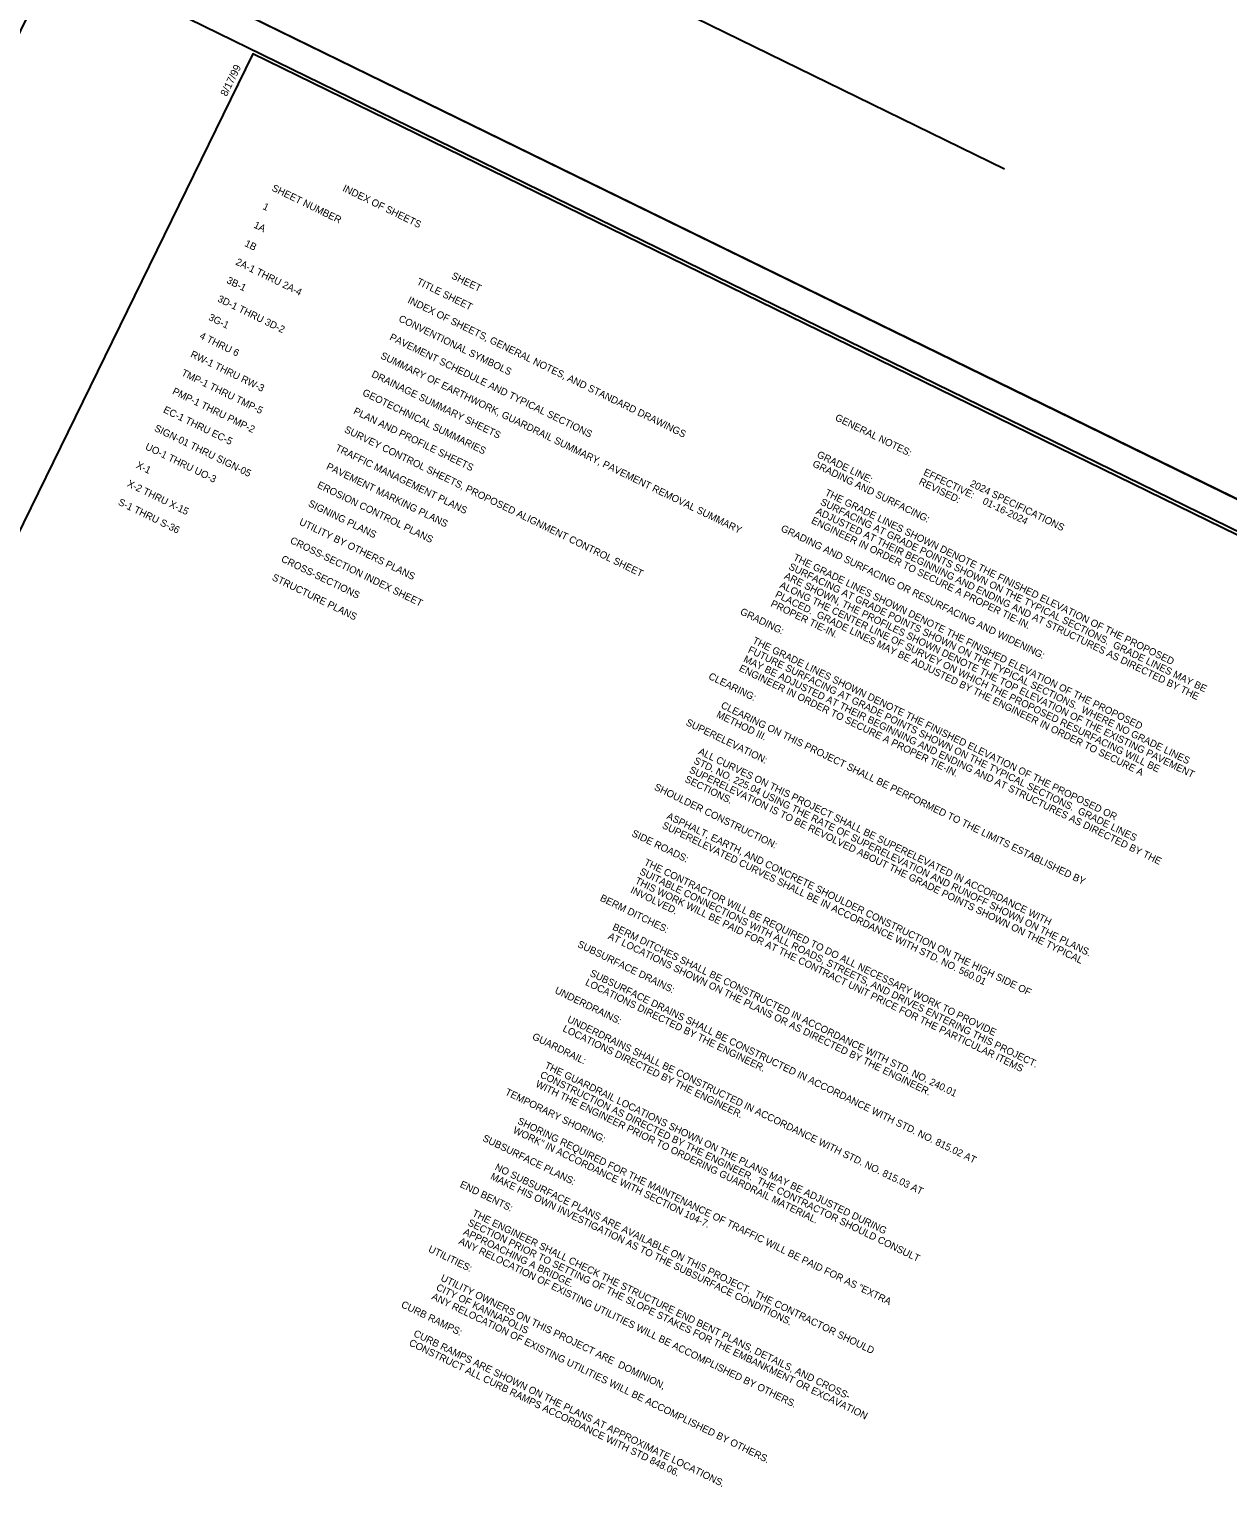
# Model space of a CAD drawing. Extents: x 1517888 to 1526099, y 633375 to 640181.
# Drawn here: x 1520060 to 1521738, y 634595 to 636669 of the extents above; entities that cross this region are included whole.
import ezdxf

# ---------------------------------------------------------------- set-up
doc = ezdxf.new("R2010")
doc.units = 0
for name, color, linetype in [('Sheet Cutting Line CELL', 7, 'Continuous'), ('Sheet Data Text CELL', 7, 'Continuous'), ('Sheet Plan CELL', 7, 'Continuous'), ('Sheet Plot Border Inside CELL', 7, 'Continuous'), ('Sheet Plot Border Outside CELL', 7, 'Continuous')]:
    doc.layers.add(name, color=color, linetype=linetype)

msp = doc.modelspace()

# ---------------------------------------------------------------- linework, layer by layer
at = {"layer": 'Sheet Cutting Line CELL'}
for p, q in [((1518399.9, 637954.2), (1521425.5, 636474.5)), ((1523118.1, 635342.8), (1520093.5, 636822.1))]:
    msp.add_line(p, q, dxfattribs=at)
at = {"layer": 'Sheet Plan CELL'}
msp.add_line((1520372.9, 636635.4), (1520372.9, 636635.4), dxfattribs=at)
msp.add_lwpolyline([(1523067.8, 635317.3), (1520372.9, 636635.4), (1519450.2, 634748.9), (1522145.2, 633430.8)], close=True, dxfattribs=at)
at = {"layer": 'Sheet Plot Border Inside CELL'}
msp.add_lwpolyline([(1519172.2, 634879.3), (1522165.4, 633415.4), (1523092.5, 635310.8), (1520099.3, 636774.7)], close=True, dxfattribs=at)
at = {"layer": 'Sheet Plot Border Outside CELL'}
msp.add_lwpolyline([(1519131.3, 634854.8), (1522155.9, 633375.5), (1523118.1, 635342.8), (1520093.5, 636822.1)], close=True, dxfattribs=at)

# ---------------------------------------------------------------- texts
at = {"layer": 'Sheet Data Text CELL'}
for s, p in [('SHEET NUMBER', (1520398.4, 636444.2)), ('                        INDEX OF SHEETS', (1520417.4, 636483)), ('1', (1520385.7, 636418.3)), ('1A', (1520373, 636392.4)), ('1B', (1520360.4, 636366.5)), ('2A-1 THRU 2A-4', (1520347.7, 636340.6)), ('3B-1', (1520335.1, 636314.8)), ('TITLE SHEET', (1520601.3, 636312.9)), ('SHEET', (1520649.9, 636321.2)), ('3D-1 THRU 3D-2', (1520322.4, 636288.9)), ('INDEX OF SHEETS, GENERAL NOTES, AND STANDARD DRAWINGS', (1520588.6, 636287)), ('3G-1', (1520309.7, 636263)), ('CONVENTIONAL SYMBOLS', (1520576, 636261.1)), ('4 THRU 6', (1520297.1, 636237.1)), ('PAVEMENT SCHEDULE AND TYPICAL SECTIONS', (1520563.3, 636235.2)), ('RW-1 THRU RW-3', (1520284.4, 636211.2)), ('SUMMARY OF EARTHWORK, GUARDRAIL SUMMARY, PAVEMENT REMOVAL SUMMARY', (1520550.6, 636209.3)), ('TMP-1 THRU TMP-5', (1520271.7, 636185.3)), ('DRAINAGE SUMMARY SHEETS', (1520538, 636183.4)), ('PMP-1 THRU PMP-2', (1520259.1, 636159.4)), ('GEOTECHNICAL SUMMARIES', (1520525.3, 636157.5)), ('EC-1 THRU EC-5', (1520246.4, 636133.5)), ('PLAN AND PROFILE SHEETS', (1520512.7, 636131.6)), ('SIGN-01 THRU SIGN-05', (1520233.8, 636107.6)), ('SURVEY CONTROL SHEETS, PROPOSED ALIGNMENT CONTROL SHEET', (1520500, 636105.8)), ('GENERAL NOTES:                         2024 SPECIFICATIONS', (1521187.3, 636122.5)), ('UO-1 THRU UO-3', (1520221.1, 636081.8)), ('TRAFFIC MANAGEMENT PLANS', (1520487.3, 636079.9)), ('GRADE LINE:  ', (1521161.9, 636070.7)), ('X-1', (1520208.4, 636055.9)), ('PAVEMENT MARKING PLANS', (1520474.7, 636054)), ('GRADING AND SURFACING:  ', (1521155.6, 636057.8)), ('                                       EFFECTIVE:    01-16-2024', (1521180.9, 636109.6)), ('X-2 THRU X-15', (1520195.8, 636030)), ('EROSION CONTROL PLANS', (1520462, 636028.1)), ('                                       REVISED:      ', (1521174.6, 636096.6)), ('S-1 THRU S-36', (1520183.1, 636004.1)), ('SIGNING PLANS', (1520449.4, 636002.2)), ('         SURFACING AT GRADE POINTS SHOWN ON THE TYPICAL SECTIONS.  GRADE LINES MAY BE ', (1521136.6, 636019)), ('         THE GRADE LINES SHOWN DENOTE THE FINISHED ELEVATION OF THE PROPOSED ', (1521142.9, 636031.9)), ('         ADJUSTED AT THEIR BEGINNING AND ENDING AND AT STRUCTURES AS DIRECTED BY THE ', (1521130.3, 636006)), ('UTILITY BY OTHERS PLANS', (1520436.7, 635976.3)), ('GRADING AND SURFACING OR RESURFACING AND WIDENING:  ', (1521111.3, 635967.2)), ('         ENGINEER IN ORDER TO SECURE A PROPER TIE-IN.  ', (1521123.9, 635993.1)), ('CROSS-SECTION INDEX SHEET', (1520424, 635950.4)), ('CROSS-SECTIONS', (1520411.4, 635924.5)), ('         THE GRADE LINES SHOWN DENOTE THE FINISHED ELEVATION OF THE PROPOSED ', (1521098.6, 635941.3)), ('STRUCTURE PLANS', (1520398.7, 635898.6)), ('         ARE SHOWN, THE PROFILES SHOWN DENOTE THE TOP ELEVATION OF THE EXISTING PAVEMENT ', (1521086, 635915.4)), ('         SURFACING AT GRADE POINTS SHOWN ON THE TYPICAL SECTIONS.  WHERE NO GRADE LINES ', (1521092.3, 635928.4)), ('         ALONG THE CENTER LINE OF SURVEY ON WHICH THE PROPOSED RESURFACING WILL BE ', (1521079.6, 635902.5)), ('         PROPER TIE-IN.  ', (1521067, 635876.6)), ('         PLACED.  GRADE LINES MAY BE ADJUSTED BY THE ENGINEER IN ORDER TO SECURE A ', (1521073.3, 635889.5)), ('GRADING:  ', (1521054.3, 635850.7)), ('         FUTURE SURFACING AT GRADE POINTS SHOWN ON THE TYPICAL SECTIONS.  GRADE LINES ', (1521035.3, 635811.9)), ('         THE GRADE LINES SHOWN DENOTE THE FINISHED ELEVATION OF THE PROPOSED OR ', (1521041.6, 635824.8)), ('         MAY BE ADJUSTED AT THEIR BEGINNING AND ENDING AND AT STRUCTURES AS DIRECTED BY THE ', (1521029, 635798.9)), ('CLEARING:  ', (1521010, 635760.1)), ('         ENGINEER IN ORDER TO SECURE A PROPER TIE-IN.  ', (1521022.7, 635786)), ('         CLEARING ON THIS PROJECT SHALL BE PERFORMED TO THE LIMITS ESTABLISHED BY ', (1520997.3, 635734.2)), ('SUPERELEVATION:  ', (1520978.3, 635695.4)), ('         METHOD III.', (1520991, 635721.3)), ('         ALL CURVES ON THIS PROJECT SHALL BE SUPERELEVATED IN ACCORDANCE WITH', (1520965.7, 635669.5)), ('         SUPERELEVATION IS TO BE REVOLVED ABOUT THE GRADE POINTS SHOWN ON THE TYPICAL ', (1520953, 635643.6)), ('         STD. NO. 225.04 USING THE RATE OF SUPERELEVATION AND RUNOFF SHOWN ON THE PLANS.', (1520959.3, 635656.5)), ('         SECTIONS.  ', (1520946.7, 635630.6)), ('SHOULDER CONSTRUCTION:  ', (1520934, 635604.8)), ('         SUPERELEVATED CURVES SHALL BE IN ACCORDANCE WITH STD. NO. 560.01', (1520915, 635565.9)), ('         ASPHALT, EARTH, AND CONCRETE SHOULDER CONSTRUCTION ON THE HIGH SIDE OF', (1520921.4, 635578.9)), ('SIDE ROADS:  ', (1520902.4, 635540)), ('         SUITABLE CONNECTIONS WITH ALL ROADS, STREETS, AND DRIVES ENTERING THIS PROJECT.  ', (1520883.4, 635501.2)), ('         THE CONTRACTOR WILL BE REQUIRED TO DO ALL NECESSARY WORK TO PROVIDE ', (1520889.7, 635514.1)), ('         THIS WORK WILL BE PAID FOR AT THE CONTRACT UNIT PRICE FOR THE PARTICULAR ITEMS ', (1520877, 635488.3)), ('BERM DITCHES:  ', (1520858.1, 635449.4)), ('         INVOLVED.  ', (1520870.7, 635475.3)), ('         BERM DITCHES SHALL BE CONSTRUCTED IN ACCORDANCE WITH STD. NO. 240.01 ', (1520845.4, 635423.5)), ('SUBSURFACE DRAINS:', (1520826.4, 635384.7)), ('         AT LOCATIONS SHOWN ON THE PLANS OR AS DIRECTED BY THE ENGINEER.  ', (1520839.1, 635410.6)), ('         SUBSURFACE DRAINS SHALL BE CONSTRUCTED IN ACCORDANCE WITH STD. NO. 815.02 AT ', (1520813.7, 635358.8)), ('UNDERDRAINS:  ', (1520794.7, 635320)), ('         LOCATIONS DIRECTED BY THE ENGINEER.  ', (1520807.4, 635345.9)), ('         UNDERDRAINS SHALL BE CONSTRUCTED IN ACCORDANCE WITH STD. NO. 815.03 AT ', (1520782.1, 635294.1)), ('GUARDRAIL:  ', (1520763.1, 635255.3)), ('         LOCATIONS DIRECTED BY THE ENGINEER.  ', (1520775.8, 635281.1)), ('         THE GUARDRAIL LOCATIONS SHOWN ON THE PLANS MAY BE ADJUSTED DURING ', (1520750.4, 635229.4)), ('         CONSTRUCTION AS DIRECTED BY THE ENGINEER.  THE CONTRACTOR SHOULD CONSULT', (1520744.1, 635216.4)), ('TEMPORARY SHORING:  ', (1520725.1, 635177.6)), ('         WITH THE ENGINEER PRIOR TO ORDERING GUARDRAIL MATERIAL.', (1520737.8, 635203.5)), ('         SHORING REQUIRED FOR THE MAINTENANCE OF TRAFFIC WILL BE PAID FOR AS "EXTRA ', (1520712.4, 635151.7)), ('SUBSURFACE PLANS:  ', (1520693.5, 635112.9)), ('         WORK" IN ACCORDANCE WITH SECTION 104-7.  ', (1520706.1, 635138.8)), ('         NO SUBSURFACE PLANS ARE AVAILABLE ON THIS PROJECT.  THE CONTRACTOR SHOULD ', (1520680.8, 635087)), ('END BENTS:  ', (1520661.8, 635048.2)), ('         MAKE HIS OWN INVESTIGATION AS TO THE SUBSURFACE CONDITIONS.  ', (1520674.5, 635074)), ('         THE ENGINEER SHALL CHECK THE STRUCTURE END BENT PLANS, DETAILS, AND CROSS-', (1520649.1, 635022.3)), ('         SECTION PRIOR TO SETTING OF THE SLOPE STAKES FOR THE EMBANKMENT OR EXCAVATION ', (1520642.8, 635009.3)), ('         ANY RELOCATION OF EXISTING UTILITIES WILL BE ACCOMPLISHED BY OTHERS.  ', (1520630.1, 634983.4)), ('         APPROACHING A BRIDGE.', (1520636.5, 634996.4)), ('UTILITIES:', (1520617.5, 634957.5)), ('         CITY OF KANNAPOLIS', (1520598.5, 634918.7)), ('         UTILITY OWNERS ON THIS PROJECT ARE  DOMINION,', (1520604.8, 634931.7)), ('         ANY RELOCATION OF EXISTING UTILITIES WILL BE ACCOMPLISHED BY OTHERS.', (1520592.2, 634905.8)), ('CURB RAMPS:', (1520579.5, 634879.9)), ('         CONSTRUCT ALL CURB RAMPS ACCORDANCE WITH STD 848.06.', (1520560.5, 634841)), ('         CURB RAMPS ARE SHOWN ON THE PLANS AT APPROXIMATE LOCATIONS.', (1520566.8, 634854))]:
    msp.add_text(s, height=10, rotation=333.9377, dxfattribs=at).set_placement(p)
at = {"layer": 'Sheet Plan CELL'}
msp.add_text('8/17/99', height=10.5, rotation=63.9377, dxfattribs=at).set_placement((1520336.1, 636575))

doc.saveas('drawing.dxf')
